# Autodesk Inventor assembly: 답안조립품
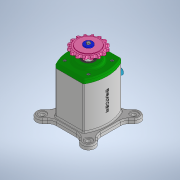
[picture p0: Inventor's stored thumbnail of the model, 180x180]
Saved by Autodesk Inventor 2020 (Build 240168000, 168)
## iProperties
Created: 2022-01
Part Number: 답안조립품
Document SubType Name: Assembly
Designer: user
Author: user
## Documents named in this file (13)
- C:\Users\user\Desktop\720117V1016\답안조립품.iam
- C:\Users\user\Desktop\720117V1016\베어링 6203.ipt
- C:\Users\user\Desktop\720117V1016\본체.ipt
- C:\Users\user\Desktop\720117V1016\볼트 M4 x 12.ipt
- C:\Users\user\Desktop\720117V1016\부시.ipt
- C:\Users\user\Desktop\720117V1016\스프로킷.ipt
- C:\Users\user\Desktop\720117V1016\슬라이더.ipt
- C:\Users\user\Desktop\720117V1016\오일 실 17 x 30 x 8.ipt
- C:\Users\user\Desktop\720117V1016\와셔 4 x 20.ipt
- C:\Users\user\Desktop\720117V1016\육각머리볼트 M4.ipt
- C:\Users\user\Desktop\720117V1016\커버.ipt
- C:\Users\user\Desktop\720117V1016\키 5 x 5.ipt
- C:\Users\user\Desktop\720117V1016\편심축.ipt
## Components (8 placed, 1 different names)
1. M4x0.7x12:2
2. M4x0.7x12:3
3. M4x0.7x12:4
4. M4x0.7x12:5
5. M4x0.7x12:1
6. M4x0.7x12:6
7. M4x0.7x12:7
8. M4x0.7x12:8
